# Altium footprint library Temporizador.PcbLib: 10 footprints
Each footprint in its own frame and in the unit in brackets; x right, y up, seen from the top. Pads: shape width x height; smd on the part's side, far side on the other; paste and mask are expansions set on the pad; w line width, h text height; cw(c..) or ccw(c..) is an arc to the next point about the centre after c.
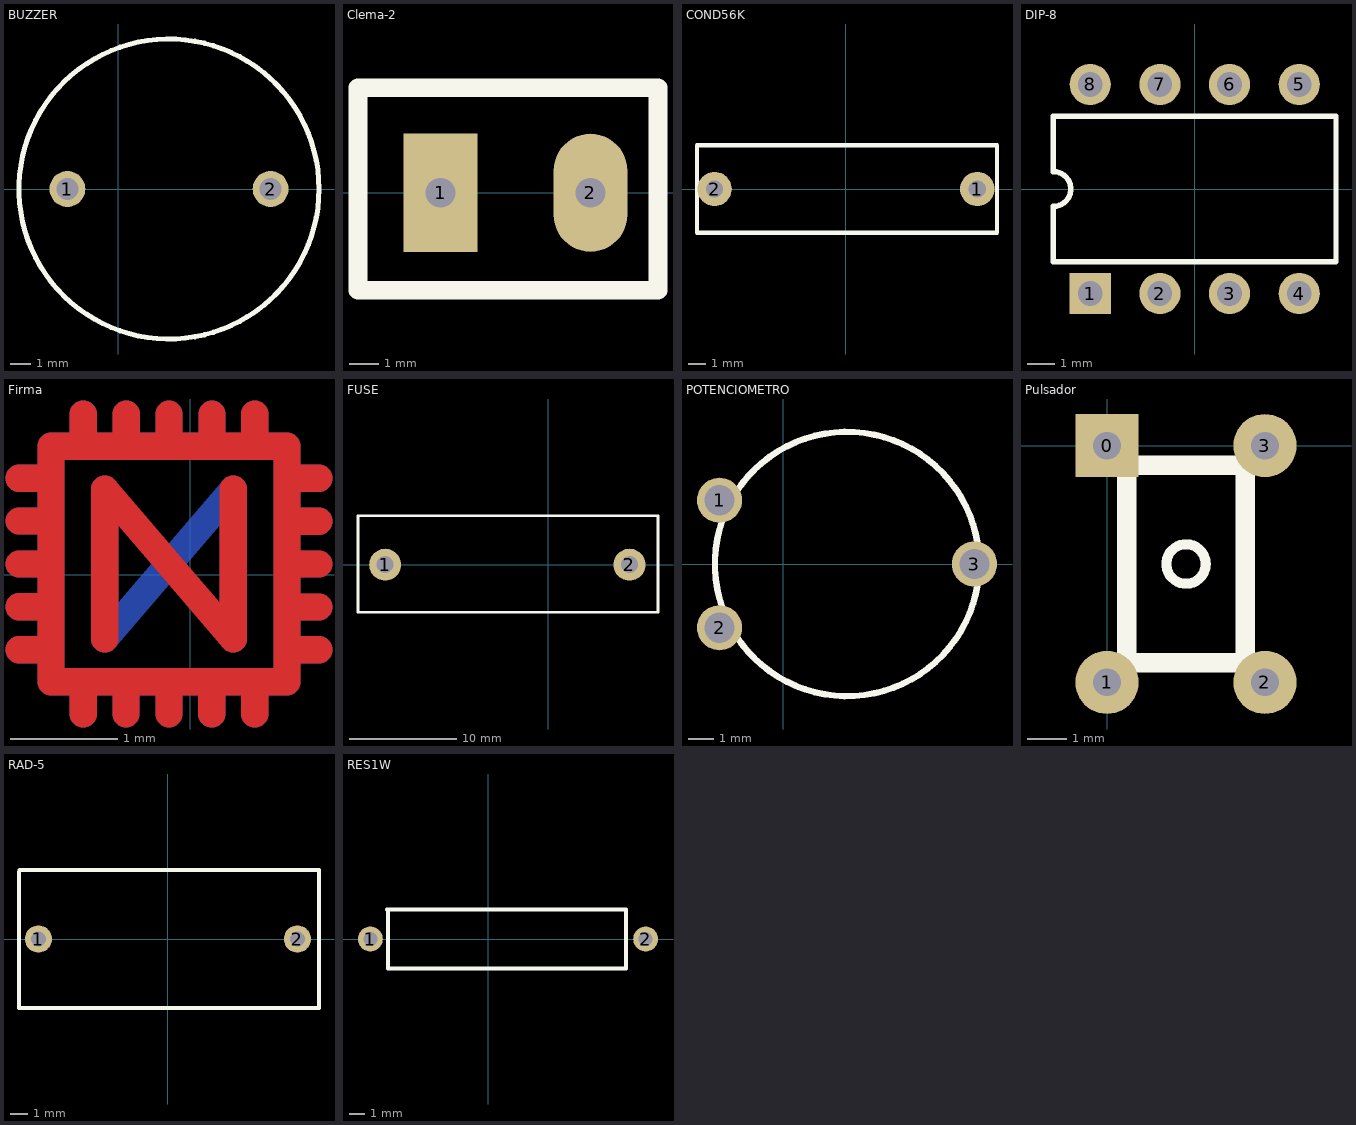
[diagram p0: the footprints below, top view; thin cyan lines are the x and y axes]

## BUZZER [mm]
pads (2):
  round 1.8 hole 1.1: 1(-2.54,0) 2(7.62,0)
Top Overlay:
  circle w0.254: c2.54,0 r7.5

## Clema-2 [mm]
pads (2):
  rect 2.5x4 hole 1: 1(3.81,0)
  oval 2.5x4 hole 1: 2(8.89,0)
Top Overlay:
  lines w0.635: 1.016,-3.302 11.176,-3.302 11.176,3.556 1.016,3.556 1.016,-3.302

## COND56K [mm]
pads (2):
  round 2 hole 1: 1(7.62,0) 2(-7.62,0)
Top Overlay:
  lines w0.254: -8.636,-2.54 -8.636,2.54 8.763,2.54 8.763,-2.54 -8.636,-2.54

## DIP-8 [mm]
pads (8):
  rect 1.5x1.5 hole 0.9: 1(-3.81,-3.81)
  round 1.5 hole 0.9: 2(-1.27,-3.81) 3(1.27,-3.81) 4(3.81,-3.81) 5(3.81,3.81) 6(1.27,3.81) 7(-1.27,3.81) 8(-3.81,3.81)
Top Overlay:
  lines w0.2: -5.15,-2.65 5.15,-2.65 5.15,2.65 -5.15,2.65 -5.15,0.635 cw(c-5.15,0) -5.15,-0.635 -5.15,-2.65

## Firma [mm] "Firma"
Top Layer:
  lines w0.254: -1.6,-0.7 -1.3,-0.7 ; -1.6,-0.3 -1.3,-0.3 ; -1.6,0.1 -1.3,0.1 ; -1.6,0.5 -1.3,0.5 ; -1.6,0.9 -1.3,0.9 ; -1,-1.3 -1,-1 ; -1,1.2 -1,1.5 ; -0.8,-0.6 -0.8,0.8 0.4,-0.6 0.4,0.8 ; -0.6,-1.3 -0.6,-1 ; -0.6,1.2 -0.6,1.5 ; -0.2,-1.3 -0.2,-1 ; -0.2,1.2 -0.2,1.5 ; 0.2,-1.3 0.2,-1 ; 0.2,1.2 0.2,1.5 ; 0.6,-1.3 0.6,-1 ; 0.6,1.2 0.6,1.5 ; 0.9,-0.7 1.2,-0.7 ; 0.9,-0.3 1.2,-0.3 ; 0.9,0.1 1.2,0.1 ; 0.9,0.5 1.2,0.5 ; 0.9,0.9 1.2,0.9 ; -1.3,-1 -1.3,1.2 0.9,1.2 0.9,-1 -1.3,-1
Bottom Layer:
  lines w0.254: -1.6,-0.7 -1.3,-0.7 ; -1.6,-0.3 -1.3,-0.3 ; -1.6,0.1 -1.3,0.1 ; -1.6,0.5 -1.3,0.5 ; -1.6,0.9 -1.3,0.9 ; -1,-1.3 -1,-1 ; -1,1.2 -1,1.5 ; -0.8,0.8 -0.8,-0.6 0.4,0.8 0.4,-0.6 ; -0.6,-1.3 -0.6,-1 ; -0.6,1.2 -0.6,1.5 ; -0.2,-1.3 -0.2,-1 ; -0.2,1.2 -0.2,1.5 ; 0.2,-1.3 0.2,-1 ; 0.2,1.2 0.2,1.5 ; 0.6,-1.3 0.6,-1 ; 0.6,1.2 0.6,1.5 ; 0.9,-0.7 1.2,-0.7 ; 0.9,-0.3 1.2,-0.3 ; 0.9,0.1 1.2,0.1 ; 0.9,0.5 1.2,0.5 ; 0.9,0.9 1.2,0.9 ; -1.3,-1 0.9,-1 0.9,1.2 -1.3,1.2 -1.3,-1

## FUSE [mm]
pads (2):
  round 3 hole 1.6: 1(-15.24,0) 2(7.62,0)
Top Overlay:
  lines w0.254: -17.78,-4.445 10.287,-4.445 10.287,4.572 -17.78,4.572 -17.78,-4.445

## POTENCIOMETRO [mm]
pads (3):
  round 1.8 hole 1.2: 1(-2.54,2.54) 2(-2.54,-2.54) 3(7.62,0)
Top Overlay:
  circle w0.254: c2.54,0 r5.269

## Pulsador [mm] "Pulsador doble circuito"
pads (4):
  rect 1.6x1.6 hole 0.7: 0(0,0)
  round 1.6 hole 0.7: 1(0,-6) 2(4,-6) 3(4,0)
Top Overlay:
  circle w0.254: c2,-3 r0.5
  lines w0.5: 0.5,-5.5 0.5,-0.5 3.5,-0.5 3.5,-5.5 0.5,-5.5

## RAD-5 [mm]
pads (2):
  round 1.6 hole 0.9: 1(-7.62,0) 2(7.62,0)
Top Overlay:
  lines w0.254: -8.763,-4.064 -8.763,3.937 -8.71,4.064 8.89,4.064 8.89,-4.064 -8.763,-4.064

## RES1W [mm]
pads (2):
  round 1.6 hole 0.9: 1(-7.62,0) 2(10.16,0)
Top Overlay:
  lines w0.254: -6.551,1.905 8.89,1.905 8.89,-1.905 -6.477,-1.905 -6.477,1.905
